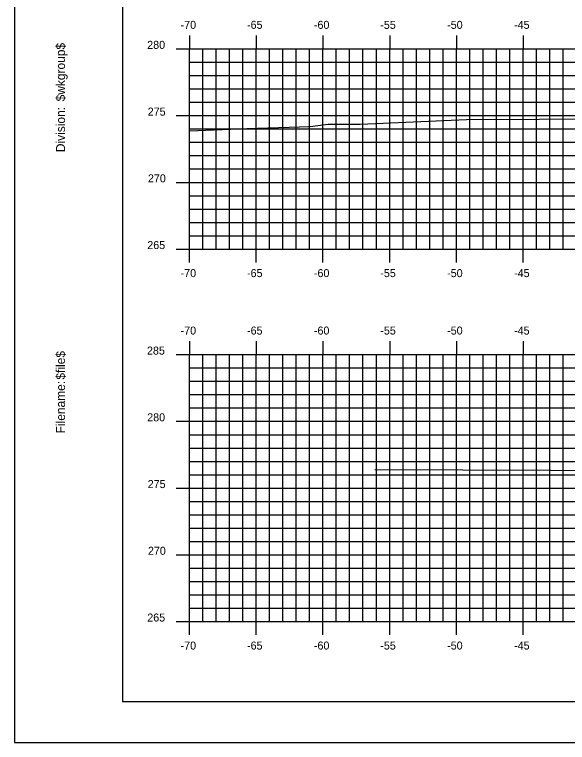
# Model space of a CAD drawing. Extents: x 854453 to 854623, y 366268 to 366378.
# Drawn here: x 854453.3 to 854494.8, y 366268.2 to 366322.7 of the extents above; entities that cross this region are included whole.
import ezdxf

# ---------------------------------------------------------------- set-up
doc = ezdxf.new("R2010")
doc.units = 0
for name, color, linetype in [('BORDER', 7, 'Continuous'), ('H_V ANNOTATION', 7, 'Continuous'), ('MAJOR', 7, 'Continuous'), ('MINOR', 7, 'Continuous'), ('PLOT BOUNDARY', 7, 'Continuous'), ('S_Roadway_Centerline', 7, 'Continuous')]:
    doc.layers.add(name, color=color, linetype=linetype)

msp = doc.modelspace()

# ---------------------------------------------------------------- linework, layer by layer
at = {"layer": 'BORDER'}
for p, q in [((854461.439, 366376.236), (854461.439, 366271.236)), ((854461.439, 366271.236), (854621.439, 366271.236))]:
    msp.add_line(p, q, dxfattribs=at)
at = {"layer": 'MAJOR'}
for p, q in [((854466.439, 366321.143), (854466.439, 366320.141)), ((854471.439, 366321.143), (854471.439, 366320.141)), ((854476.439, 366321.143), (854476.439, 366320.141)), ((854481.439, 366321.143), (854481.439, 366320.141)), ((854486.439, 366321.143), (854486.439, 366320.141)), ((854491.439, 366321.143), (854491.439, 366320.141)), ((854465.437, 366320.141), (854466.439, 366320.141)), ((854466.439, 366320.141), (854606.439, 366320.141)), ((854466.439, 366305.141), (854466.439, 366320.141)), ((854466.439, 366305.141), (854466.439, 366320.141)), ((854466.439, 366320.141), (854606.439, 366320.141)), ((854471.439, 366305.141), (854471.439, 366320.141)), ((854476.439, 366305.141), (854476.439, 366320.141)), ((854481.439, 366305.141), (854481.439, 366320.141)), ((854486.439, 366305.141), (854486.439, 366320.141)), ((854491.439, 366305.141), (854491.439, 366320.141)), ((854465.437, 366315.141), (854466.439, 366315.141)), ((854466.439, 366315.141), (854606.439, 366315.141)), ((854465.437, 366310.141), (854466.439, 366310.141)), ((854466.439, 366310.141), (854606.439, 366310.141)), ((854465.437, 366305.141), (854466.439, 366305.141)), ((854466.439, 366305.141), (854606.439, 366305.141)), ((854466.439, 366305.141), (854606.439, 366305.141)), ((854466.439, 366304.139), (854466.439, 366305.141)), ((854471.439, 366304.139), (854471.439, 366305.141)), ((854476.439, 366304.139), (854476.439, 366305.141)), ((854481.439, 366304.139), (854481.439, 366305.141)), ((854486.439, 366304.139), (854486.439, 366305.141)), ((854491.439, 366304.139), (854491.439, 366305.141)), ((854466.439, 366298.238), (854466.439, 366297.236)), ((854471.439, 366298.238), (854471.439, 366297.236)), ((854476.439, 366298.238), (854476.439, 366297.236)), ((854481.439, 366298.238), (854481.439, 366297.236)), ((854486.439, 366298.238), (854486.439, 366297.236)), ((854491.439, 366298.238), (854491.439, 366297.236)), ((854465.437, 366297.236), (854466.439, 366297.236)), ((854466.439, 366297.236), (854606.439, 366297.236)), ((854466.439, 366277.236), (854466.439, 366297.236)), ((854466.439, 366277.236), (854466.439, 366297.236)), ((854466.439, 366297.236), (854606.439, 366297.236)), ((854471.439, 366277.236), (854471.439, 366297.236)), ((854476.439, 366277.236), (854476.439, 366297.236)), ((854481.439, 366277.236), (854481.439, 366297.236)), ((854486.439, 366277.236), (854486.439, 366297.236)), ((854491.439, 366277.236), (854491.439, 366297.236)), ((854465.437, 366292.236), (854466.439, 366292.236)), ((854466.439, 366292.236), (854606.439, 366292.236)), ((854465.437, 366287.236), (854466.439, 366287.236)), ((854466.439, 366287.236), (854606.439, 366287.236)), ((854465.437, 366282.236), (854466.439, 366282.236)), ((854466.439, 366282.236), (854606.439, 366282.236)), ((854465.437, 366277.236), (854466.439, 366277.236)), ((854466.439, 366277.236), (854606.439, 366277.236)), ((854466.439, 366277.236), (854606.439, 366277.236)), ((854466.439, 366276.234), (854466.439, 366277.236)), ((854471.439, 366276.234), (854471.439, 366277.236)), ((854476.439, 366276.234), (854476.439, 366277.236)), ((854481.439, 366276.234), (854481.439, 366277.236)), ((854486.439, 366276.234), (854486.439, 366277.236)), ((854491.439, 366276.234), (854491.439, 366277.236))]:
    msp.add_line(p, q, dxfattribs=at)
at = {"layer": 'MINOR'}
for p, q in [((854466.439, 366305.141), (854466.439, 366320.141)), ((854467.439, 366305.141), (854467.439, 366320.141)), ((854468.439, 366305.141), (854468.439, 366320.141)), ((854469.439, 366305.141), (854469.439, 366320.141)), ((854470.439, 366305.141), (854470.439, 366320.141)), ((854472.439, 366305.141), (854472.439, 366320.141)), ((854473.439, 366305.141), (854473.439, 366320.141)), ((854474.439, 366305.141), (854474.439, 366320.141)), ((854475.439, 366305.141), (854475.439, 366320.141)), ((854477.439, 366305.141), (854477.439, 366320.141)), ((854478.439, 366305.141), (854478.439, 366320.141)), ((854479.439, 366305.141), (854479.439, 366320.141)), ((854480.439, 366305.141), (854480.439, 366320.141)), ((854482.439, 366305.141), (854482.439, 366320.141)), ((854483.439, 366305.141), (854483.439, 366320.141)), ((854484.439, 366305.141), (854484.439, 366320.141)), ((854485.439, 366305.141), (854485.439, 366320.141)), ((854487.439, 366305.141), (854487.439, 366320.141)), ((854488.439, 366305.141), (854488.439, 366320.141)), ((854489.439, 366305.141), (854489.439, 366320.141)), ((854490.439, 366305.141), (854490.439, 366320.141)), ((854492.439, 366305.141), (854492.439, 366320.141)), ((854493.439, 366305.141), (854493.439, 366320.141)), ((854494.439, 366305.141), (854494.439, 366320.141)), ((854466.439, 366319.141), (854606.439, 366319.141)), ((854466.439, 366319.141), (854467.441, 366319.141)), ((854466.439, 366318.141), (854606.439, 366318.141)), ((854466.439, 366318.141), (854467.441, 366318.141)), ((854466.439, 366317.141), (854606.439, 366317.141)), ((854466.439, 366317.141), (854467.441, 366317.141)), ((854466.439, 366316.141), (854606.439, 366316.141)), ((854466.439, 366316.141), (854467.441, 366316.141)), ((854466.439, 366314.141), (854606.439, 366314.141)), ((854466.439, 366314.141), (854467.441, 366314.141)), ((854466.439, 366313.141), (854606.439, 366313.141)), ((854466.439, 366313.141), (854467.441, 366313.141)), ((854466.439, 366312.141), (854606.439, 366312.141)), ((854466.439, 366312.141), (854467.441, 366312.141)), ((854466.439, 366311.141), (854606.439, 366311.141)), ((854466.439, 366311.141), (854467.441, 366311.141)), ((854466.439, 366309.141), (854606.439, 366309.141)), ((854466.439, 366309.141), (854467.441, 366309.141)), ((854466.439, 366308.141), (854606.439, 366308.141)), ((854466.439, 366308.141), (854467.441, 366308.141)), ((854466.439, 366307.141), (854606.439, 366307.141)), ((854466.439, 366307.141), (854467.441, 366307.141)), ((854466.439, 366306.141), (854606.439, 366306.141)), ((854466.439, 366306.141), (854467.441, 366306.141)), ((854467.439, 366277.236), (854467.439, 366297.236)), ((854468.439, 366277.236), (854468.439, 366297.236)), ((854469.439, 366277.236), (854469.439, 366297.236)), ((854470.439, 366277.236), (854470.439, 366297.236)), ((854472.439, 366277.236), (854472.439, 366297.236)), ((854473.439, 366277.236), (854473.439, 366297.236)), ((854474.439, 366277.236), (854474.439, 366297.236)), ((854475.439, 366277.236), (854475.439, 366297.236)), ((854477.439, 366277.236), (854477.439, 366297.236)), ((854478.439, 366277.236), (854478.439, 366297.236)), ((854479.439, 366277.236), (854479.439, 366297.236)), ((854480.439, 366277.236), (854480.439, 366297.236)), ((854482.439, 366277.236), (854482.439, 366297.236)), ((854483.439, 366277.236), (854483.439, 366297.236)), ((854484.439, 366277.236), (854484.439, 366297.236)), ((854485.439, 366277.236), (854485.439, 366297.236)), ((854487.439, 366277.236), (854487.439, 366297.236)), ((854488.439, 366277.236), (854488.439, 366297.236)), ((854489.439, 366277.236), (854489.439, 366297.236)), ((854490.439, 366277.236), (854490.439, 366297.236)), ((854492.439, 366277.236), (854492.439, 366297.236)), ((854493.439, 366277.236), (854493.439, 366297.236)), ((854494.439, 366277.236), (854494.439, 366297.236)), ((854466.439, 366296.236), (854606.439, 366296.236)), ((854466.439, 366296.236), (854467.441, 366296.236)), ((854466.439, 366295.236), (854606.439, 366295.236)), ((854466.439, 366295.236), (854467.441, 366295.236)), ((854466.439, 366294.236), (854606.439, 366294.236)), ((854466.439, 366294.236), (854467.441, 366294.236)), ((854466.439, 366293.236), (854606.439, 366293.236)), ((854466.439, 366293.236), (854467.441, 366293.236)), ((854466.439, 366291.236), (854606.439, 366291.236)), ((854466.439, 366291.236), (854467.441, 366291.236)), ((854466.439, 366290.236), (854606.439, 366290.236)), ((854466.439, 366290.236), (854467.441, 366290.236)), ((854466.439, 366289.236), (854606.439, 366289.236)), ((854466.439, 366289.236), (854467.441, 366289.236)), ((854466.439, 366288.236), (854606.439, 366288.236)), ((854466.439, 366288.236), (854467.441, 366288.236)), ((854466.439, 366286.236), (854606.439, 366286.236)), ((854466.439, 366286.236), (854467.441, 366286.236)), ((854466.439, 366285.236), (854606.439, 366285.236)), ((854466.439, 366285.236), (854467.441, 366285.236)), ((854466.439, 366284.236), (854606.439, 366284.236)), ((854466.439, 366284.236), (854467.441, 366284.236)), ((854466.439, 366283.236), (854606.439, 366283.236)), ((854466.439, 366283.236), (854467.441, 366283.236)), ((854466.439, 366281.236), (854606.439, 366281.236)), ((854466.439, 366281.236), (854467.441, 366281.236)), ((854466.439, 366280.236), (854606.439, 366280.236)), ((854466.439, 366280.236), (854467.441, 366280.236)), ((854466.439, 366279.236), (854606.439, 366279.236)), ((854466.439, 366279.236), (854467.441, 366279.236)), ((854466.439, 366278.236), (854606.439, 366278.236)), ((854466.439, 366278.236), (854467.441, 366278.236))]:
    msp.add_line(p, q, dxfattribs=at)
at = {"layer": 'PLOT BOUNDARY'}
msp.add_lwpolyline([(854453.345, 366268.177), (854623.345, 366268.177), (854623.345, 366378.177), (854453.345, 366378.177)], close=True, dxfattribs=at)
at = {"layer": 'S_Roadway_Centerline'}
for points in [[(854466.439, 366314.002), (854470.74, 366314.183), (854475.481, 366314.333), (854476.831, 366314.492), (854479.229, 366314.495), (854487.191, 366314.837), (854498.101, 366314.894)], [(854480.334, 366288.633), (854493.517, 366288.569), (854495.355, 366288.554)]]:
    msp.add_lwpolyline(points, dxfattribs=at)

# ---------------------------------------------------------------- texts
at = {"layer": 'BORDER'}
for s, p in [('$wkgroup$', (854457.124, 366316.206)), ('Division:', (854457.124, 366312.403)), ('$file$', (854457.124, 366295.362)), ('Filename:', (854457.124, 366291.335))]:
    msp.add_text(s, height=0.6696, rotation=90, dxfattribs=at).set_placement(p)
at = {"layer": 'H_V ANNOTATION'}
for s, p in [('-70', (854465.78, 366321.641)), ('-65', (854470.756, 366321.641)), ('-60', (854475.764, 366321.641)), ('-55', (854480.735, 366321.641)), ('-50', (854485.743, 366321.641)), ('-45', (854490.756, 366321.641)), ('280', (854463.279, 366320.141)), ('275', (854463.317, 366315.141)), ('270', (854463.333, 366310.141)), ('265', (854463.285, 366305.141)), ('-70', (854465.78, 366303.041)), ('-65', (854470.756, 366303.041)), ('-60', (854475.764, 366303.041)), ('-55', (854480.735, 366303.041)), ('-50', (854485.743, 366303.041)), ('-45', (854490.756, 366303.041)), ('-70', (854465.78, 366298.736)), ('-65', (854470.756, 366298.736)), ('-60', (854475.764, 366298.736)), ('-55', (854480.735, 366298.736)), ('-50', (854485.743, 366298.736)), ('-45', (854490.756, 366298.736)), ('285', (854463.263, 366297.236)), ('280', (854463.279, 366292.236)), ('275', (854463.317, 366287.236)), ('270', (854463.333, 366282.236)), ('265', (854463.285, 366277.236)), ('-70', (854465.78, 366275.136)), ('-65', (854470.756, 366275.136)), ('-60', (854475.764, 366275.136)), ('-55', (854480.735, 366275.136)), ('-50', (854485.743, 366275.136)), ('-45', (854490.756, 366275.136))]:
    msp.add_text(s, height=0.6, dxfattribs=at).set_placement(p)
at = {"layer": 'MAJOR'}
for p in [(854466.434, 366305.141), (854466.434, 366277.236)]:
    msp.add_text('-', height=0.00000006, rotation=53.1301, dxfattribs=at).set_placement(p)

doc.saveas('drawing.dxf')
